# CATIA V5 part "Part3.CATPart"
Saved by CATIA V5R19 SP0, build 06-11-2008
Part number: Part3
Bounding box of the stored display mesh (mm): x 10 to 10, y -103.562 to -103.562, z 31.77 to 111.77
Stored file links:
  D:\Shriniwas\v5_r19\c16_CAT_v5r19\c16_Part\Sperical Joint\Part3.CATPart
  D:\Shriniwas\v5_r19\c16_CAT_v5r19\c16_Part\Sperical Joint\Product1_mechanisam.CATProduct
  D:\Shriniwas\v5_r19\c16_CAT_v5r19\c16_Part\Sperical Joint\Part1.CATPart
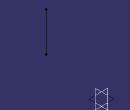
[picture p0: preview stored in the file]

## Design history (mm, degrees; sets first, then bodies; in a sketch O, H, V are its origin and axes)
Set1
  Plane1: linked copy from another document
Body1 (main body)
  Sketch1 on Plane1, origin (0, -103.5621, 0), H (-1, 0, 0), V (0, 0, 1)
    line L1 (-10, 111.7697) -> (-10, 31.7697)
    vertical: L1 V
